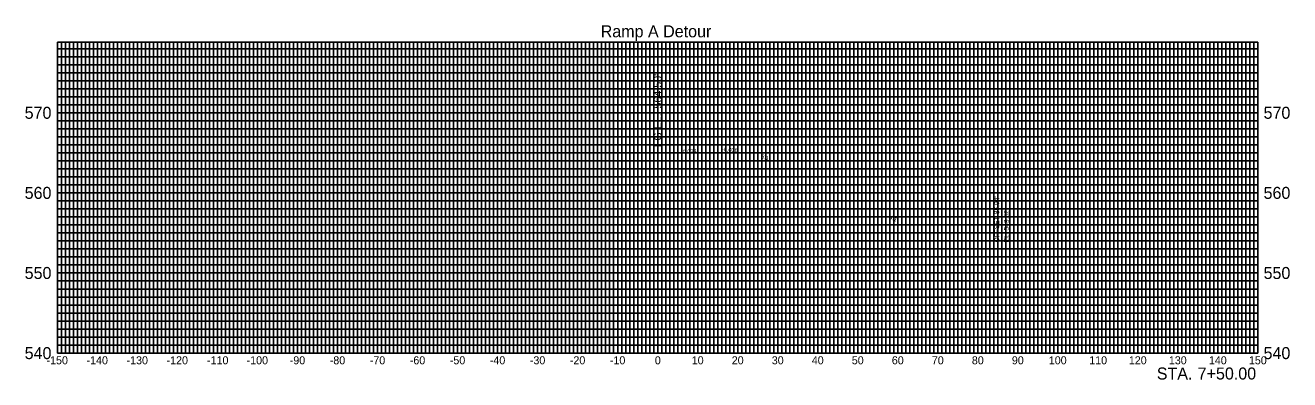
# Model space of a CAD drawing. Extents: x -158 to 158, y 533 to 622.
import ezdxf

# ---------------------------------------------------------------- set-up
doc = ezdxf.new("R2010")
doc.units = 0
for name, color, linetype in [('DES - SHEET - Light Grid', 7, 'Continuous'), ('DES - SHEET - Linework', 7, 'Continuous'), ('DES - XS - Proposed - Finished Grade Slopes Text', 7, 'Continuous'), ('DES - XS - Proposed - Text', 7, 'Continuous')]:
    doc.layers.add(name, color=color, linetype=linetype)

msp = doc.modelspace()

# ---------------------------------------------------------------- linework, layer by layer
at = {"layer": 'DES - SHEET - Light Grid'}
for p, q in [((-149, 540), (-149, 617.64)), ((-148, 540), (-148, 617.64)), ((-147, 540), (-147, 617.64)), ((-146, 540), (-146, 617.64)), ((-145, 540), (-145, 617.64)), ((-144, 540), (-144, 617.64)), ((-143, 540), (-143, 617.64)), ((-142, 540), (-142, 617.64)), ((-141, 540), (-141, 617.64)), ((-139, 540), (-139, 617.64)), ((-138, 540), (-138, 617.64)), ((-137, 540), (-137, 617.64)), ((-136, 540), (-136, 617.64)), ((-135, 540), (-135, 617.64)), ((-134, 540), (-134, 617.64)), ((-133, 540), (-133, 617.64)), ((-132, 540), (-132, 617.64)), ((-131, 540), (-131, 617.64)), ((-129, 540), (-129, 617.64)), ((-128, 540), (-128, 617.64)), ((-127, 540), (-127, 617.64)), ((-126, 540), (-126, 617.64)), ((-125, 540), (-125, 617.64)), ((-124, 540), (-124, 617.64)), ((-123, 540), (-123, 617.64)), ((-122, 540), (-122, 617.64)), ((-121, 540), (-121, 617.64)), ((-119, 540), (-119, 617.64)), ((-118, 540), (-118, 617.64)), ((-117, 540), (-117, 617.64)), ((-116, 540), (-116, 617.64)), ((-115, 540), (-115, 617.64)), ((-114, 540), (-114, 617.64)), ((-113, 540), (-113, 617.64)), ((-112, 540), (-112, 617.64)), ((-111, 540), (-111, 617.64)), ((-109, 540), (-109, 617.64)), ((-108, 540), (-108, 617.64)), ((-107, 540), (-107, 617.64)), ((-106, 540), (-106, 617.64)), ((-105, 540), (-105, 617.64)), ((-104, 540), (-104, 617.64)), ((-103, 540), (-103, 617.64)), ((-102, 540), (-102, 617.64)), ((-101, 540), (-101, 617.64)), ((-99, 540), (-99, 617.64)), ((-98, 540), (-98, 617.64)), ((-97, 540), (-97, 617.64)), ((-96, 540), (-96, 617.64)), ((-95, 540), (-95, 617.64)), ((-94, 540), (-94, 617.64)), ((-93, 540), (-93, 617.64)), ((-92, 540), (-92, 617.64)), ((-91, 540), (-91, 617.64)), ((-89, 540), (-89, 617.64)), ((-88, 540), (-88, 617.64)), ((-87, 540), (-87, 617.64)), ((-86, 540), (-86, 617.64)), ((-85, 540), (-85, 617.64)), ((-84, 540), (-84, 617.64)), ((-83, 540), (-83, 617.64)), ((-82, 540), (-82, 617.64)), ((-81, 540), (-81, 617.64)), ((-79, 540), (-79, 617.64)), ((-78, 540), (-78, 617.64)), ((-77, 540), (-77, 617.64)), ((-76, 540), (-76, 617.64)), ((-75, 540), (-75, 617.64)), ((-74, 540), (-74, 617.64)), ((-73, 540), (-73, 617.64)), ((-72, 540), (-72, 617.64)), ((-71, 540), (-71, 617.64)), ((-69, 540), (-69, 617.64)), ((-68, 540), (-68, 617.64)), ((-67, 540), (-67, 617.64)), ((-66, 540), (-66, 617.64)), ((-65, 540), (-65, 617.64)), ((-64, 540), (-64, 617.64)), ((-63, 540), (-63, 617.64)), ((-62, 540), (-62, 617.64)), ((-61, 540), (-61, 617.64)), ((-59, 540), (-59, 617.64)), ((-58, 540), (-58, 617.64)), ((-57, 540), (-57, 617.64)), ((-56, 540), (-56, 617.64)), ((-55, 540), (-55, 617.64)), ((-54, 540), (-54, 617.64)), ((-53, 540), (-53, 617.64)), ((-52, 540), (-52, 617.64)), ((-51, 540), (-51, 617.64)), ((-49, 540), (-49, 617.64)), ((-48, 540), (-48, 617.64)), ((-47, 540), (-47, 617.64)), ((-46, 540), (-46, 617.64)), ((-45, 540), (-45, 617.64)), ((-44, 540), (-44, 617.64)), ((-43, 540), (-43, 617.64)), ((-42, 540), (-42, 617.64)), ((-41, 540), (-41, 617.64)), ((-39, 540), (-39, 617.64)), ((-38, 540), (-38, 617.64)), ((-37, 540), (-37, 617.64)), ((-36, 540), (-36, 617.64)), ((-35, 540), (-35, 617.64)), ((-34, 540), (-34, 617.64)), ((-33, 540), (-33, 617.64)), ((-32, 540), (-32, 617.64)), ((-31, 540), (-31, 617.64)), ((-29, 540), (-29, 617.64)), ((-28, 540), (-28, 617.64)), ((-27, 540), (-27, 617.64)), ((-26, 540), (-26, 617.64)), ((-25, 540), (-25, 617.64)), ((-24, 540), (-24, 617.64)), ((-23, 540), (-23, 617.64)), ((-22, 540), (-22, 617.64)), ((-21, 540), (-21, 617.64)), ((-19, 540), (-19, 617.64)), ((-18, 540), (-18, 617.64)), ((-17, 540), (-17, 617.64)), ((-16, 540), (-16, 617.64)), ((-15, 540), (-15, 617.64)), ((-14, 540), (-14, 617.64)), ((-13, 540), (-13, 617.64)), ((-12, 540), (-12, 617.64)), ((-11, 540), (-11, 617.64)), ((-9, 540), (-9, 617.64)), ((-8, 540), (-8, 617.64)), ((-7, 540), (-7, 617.64)), ((-6, 540), (-6, 617.64)), ((-5, 540), (-5, 617.64)), ((-4, 540), (-4, 617.64)), ((-3, 540), (-3, 617.64)), ((-2, 540), (-2, 617.64)), ((-1, 540), (-1, 617.64)), ((1, 540), (1, 617.64)), ((2, 540), (2, 617.64)), ((3, 540), (3, 617.64)), ((4, 540), (4, 617.64)), ((5, 540), (5, 617.64)), ((6, 540), (6, 617.64)), ((7, 540), (7, 617.64)), ((8, 540), (8, 617.64)), ((9, 540), (9, 617.64)), ((11, 540), (11, 617.64)), ((12, 540), (12, 617.64)), ((13, 540), (13, 617.64)), ((14, 540), (14, 617.64)), ((15, 540), (15, 617.64)), ((16, 540), (16, 617.64)), ((17, 540), (17, 617.64)), ((18, 540), (18, 617.64)), ((19, 540), (19, 617.64)), ((21, 540), (21, 617.64)), ((22, 540), (22, 617.64)), ((23, 540), (23, 617.64)), ((24, 540), (24, 617.64)), ((25, 540), (25, 617.64)), ((26, 540), (26, 617.64)), ((27, 540), (27, 617.64)), ((28, 540), (28, 617.64)), ((29, 540), (29, 617.64)), ((31, 540), (31, 617.64)), ((32, 540), (32, 617.64)), ((33, 540), (33, 617.64)), ((34, 540), (34, 617.64)), ((35, 540), (35, 617.64)), ((36, 540), (36, 617.64)), ((37, 540), (37, 617.64)), ((38, 540), (38, 617.64)), ((39, 540), (39, 617.64)), ((41, 540), (41, 617.64)), ((42, 540), (42, 617.64)), ((43, 540), (43, 617.64)), ((44, 540), (44, 617.64)), ((45, 540), (45, 617.64)), ((46, 540), (46, 617.64)), ((47, 540), (47, 617.64)), ((48, 540), (48, 617.64)), ((49, 540), (49, 617.64)), ((51, 540), (51, 617.64)), ((52, 540), (52, 617.64)), ((53, 540), (53, 617.64)), ((54, 540), (54, 617.64)), ((55, 540), (55, 617.64)), ((56, 540), (56, 617.64)), ((57, 540), (57, 617.64)), ((58, 540), (58, 617.64)), ((59, 540), (59, 617.64)), ((61, 540), (61, 617.64)), ((62, 540), (62, 617.64)), ((63, 540), (63, 617.64)), ((64, 540), (64, 617.64)), ((65, 540), (65, 617.64)), ((66, 540), (66, 617.64)), ((67, 540), (67, 617.64)), ((68, 540), (68, 617.64)), ((69, 540), (69, 617.64)), ((71, 540), (71, 617.64)), ((72, 540), (72, 617.64)), ((73, 540), (73, 617.64)), ((74, 540), (74, 617.64)), ((75, 540), (75, 617.64)), ((76, 540), (76, 617.64)), ((77, 540), (77, 617.64)), ((78, 540), (78, 617.64)), ((79, 540), (79, 617.64)), ((81, 540), (81, 617.64)), ((82, 540), (82, 617.64)), ((83, 540), (83, 617.64)), ((84, 540), (84, 617.64)), ((85, 540), (85, 617.64)), ((86, 540), (86, 617.64)), ((87, 540), (87, 617.64)), ((88, 540), (88, 617.64)), ((89, 540), (89, 617.64)), ((91, 540), (91, 617.64)), ((92, 540), (92, 617.64)), ((93, 540), (93, 617.64)), ((94, 540), (94, 617.64)), ((95, 540), (95, 617.64)), ((96, 540), (96, 617.64)), ((97, 540), (97, 617.64)), ((98, 540), (98, 617.64)), ((99, 540), (99, 617.64)), ((101, 540), (101, 617.64)), ((102, 540), (102, 617.64)), ((103, 540), (103, 617.64)), ((104, 540), (104, 617.64)), ((105, 540), (105, 617.64)), ((106, 540), (106, 617.64)), ((107, 540), (107, 617.64)), ((108, 540), (108, 617.64)), ((109, 540), (109, 617.64)), ((111, 540), (111, 617.64)), ((112, 540), (112, 617.64)), ((113, 540), (113, 617.64)), ((114, 540), (114, 617.64)), ((115, 540), (115, 617.64)), ((116, 540), (116, 617.64)), ((117, 540), (117, 617.64)), ((118, 540), (118, 617.64)), ((119, 540), (119, 617.64)), ((121, 540), (121, 617.64)), ((122, 540), (122, 617.64)), ((123, 540), (123, 617.64)), ((124, 540), (124, 617.64)), ((125, 540), (125, 617.64)), ((126, 540), (126, 617.64)), ((127, 540), (127, 617.64)), ((128, 540), (128, 617.64)), ((129, 540), (129, 617.64)), ((131, 540), (131, 617.64)), ((132, 540), (132, 617.64)), ((133, 540), (133, 617.64)), ((134, 540), (134, 617.64)), ((135, 540), (135, 617.64)), ((136, 540), (136, 617.64)), ((137, 540), (137, 617.64)), ((138, 540), (138, 617.64)), ((139, 540), (139, 617.64)), ((141, 540), (141, 617.64)), ((142, 540), (142, 617.64)), ((143, 540), (143, 617.64)), ((144, 540), (144, 617.64)), ((145, 540), (145, 617.64)), ((146, 540), (146, 617.64)), ((147, 540), (147, 617.64)), ((148, 540), (148, 617.64)), ((149, 540), (149, 617.64)), ((-150, 616), (150, 616)), ((-150, 614), (150, 614)), ((-150, 612), (150, 612)), ((-150, 610), (150, 610)), ((-150, 608), (150, 608)), ((-150, 606), (150, 606)), ((-150, 604), (150, 604)), ((-150, 602), (150, 602)), ((-150, 598), (150, 598)), ((-150, 596), (150, 596)), ((-150, 594), (150, 594)), ((-150, 592), (150, 592)), ((-150, 590), (150, 590)), ((-150, 588), (150, 588)), ((-150, 586), (150, 586)), ((-150, 584), (150, 584)), ((-150, 582), (150, 582)), ((-150, 578), (150, 578)), ((-150, 576), (150, 576)), ((-150, 574), (150, 574)), ((-150, 572), (150, 572)), ((-150, 570), (150, 570)), ((-150, 568), (150, 568)), ((-150, 566), (150, 566)), ((-150, 564), (150, 564)), ((-150, 562), (150, 562)), ((-150, 558), (150, 558)), ((-150, 556), (150, 556)), ((-150, 554), (150, 554)), ((-150, 552), (150, 552)), ((-150, 550), (150, 550)), ((-150, 548), (150, 548)), ((-150, 546), (150, 546)), ((-150, 544), (150, 544)), ((-150, 542), (150, 542))]:
    msp.add_line(p, q, dxfattribs=at)
at = {"layer": 'DES - SHEET - Linework'}
for p, q in [((-150, 617.64), (150, 617.64)), ((-150, 540), (-150, 617.64)), ((-140, 540), (-140, 617.64)), ((-130, 540), (-130, 617.64)), ((-120, 540), (-120, 617.64)), ((-110, 540), (-110, 617.64)), ((-100, 540), (-100, 617.64)), ((-90, 540), (-90, 617.64)), ((-80, 540), (-80, 617.64)), ((-70, 540), (-70, 617.64)), ((-60, 540), (-60, 617.64)), ((-50, 540), (-50, 617.64)), ((-40, 540), (-40, 617.64)), ((-30, 540), (-30, 617.64)), ((-20, 540), (-20, 617.64)), ((-10, 540), (-10, 617.64)), ((0, 540), (0, 617.64)), ((10, 540), (10, 617.64)), ((20, 540), (20, 617.64)), ((30, 540), (30, 617.64)), ((40, 540), (40, 617.64)), ((50, 540), (50, 617.64)), ((60, 540), (60, 617.64)), ((70, 540), (70, 617.64)), ((80, 540), (80, 617.64)), ((90, 540), (90, 617.64)), ((100, 540), (100, 617.64)), ((110, 540), (110, 617.64)), ((120, 540), (120, 617.64)), ((130, 540), (130, 617.64)), ((140, 540), (140, 617.64)), ((150, 540), (150, 617.64)), ((-150, 600), (150, 600)), ((-150, 580), (150, 580)), ((-150, 560), (150, 560)), ((-150, 540), (150, 540))]:
    msp.add_line(p, q, dxfattribs=at)

# ---------------------------------------------------------------- texts
at = {"layer": 'DES - XS - Proposed - Finished Grade Slopes Text'}
for s, height, rotation, p in [('0.034', 1, 3.922, (6.29, 589.74)), ('-0.036', 1, 355.9137, (16.06, 590.4)), ('6:1', 1, 341.5651, (25.78, 588.72)), ("85.94'", 1.2, 90, (85.34, 574.68)), ('549.62', 1.2, 90, (87.74, 570.61)), ('4:1', 1, 333.4349, (57.79, 573.61)), ('OFFSET ', 1.2, 90, (85.34, 567.63)), ('EL. ', 1.2, 90, (87.74, 567.63))]:
    msp.add_text(s, height=height, rotation=rotation, dxfattribs=at).set_placement(p)
at = {"layer": 'DES - XS - Proposed - Text'}
for s, height, p in [('Ramp A Detour', 3, (-14.24, 618.84)), ('570', 3, (-158.19, 598.5)), ('570', 3, (151.41, 598.5)), ('560', 3, (-158.19, 578.5)), ('560', 3, (151.41, 578.5)), ('550', 3, (-158.19, 558.5)), ('550', 3, (151.41, 558.5)), ('540', 3, (-158.19, 538.5)), ('540', 3, (151.41, 538.5)), ('-150', 2, (-152.73, 537.2)), ('-140', 2, (-142.73, 537.2)), ('-130', 2, (-132.73, 537.2)), ('-120', 2, (-122.73, 537.2)), ('-110', 2, (-112.62, 537.2)), ('-100', 2, (-102.73, 537.2)), ('-90', 2, (-91.95, 537.2)), ('-80', 2, (-81.95, 537.2)), ('-70', 2, (-71.95, 537.2)), ('-60', 2, (-61.95, 537.2)), ('-50', 2, (-51.95, 537.2)), ('-40', 2, (-41.95, 537.2)), ('-30', 2, (-31.95, 537.2)), ('-20', 2, (-21.95, 537.2)), ('-10', 2, (-11.95, 537.2)), ('0', 2, (-0.71, 537.2)), ('10', 2, (8.51, 537.2)), ('20', 2, (18.51, 537.2)), ('30', 2, (28.51, 537.2)), ('40', 2, (38.51, 537.2)), ('50', 2, (48.51, 537.2)), ('60', 2, (58.51, 537.2)), ('70', 2, (68.51, 537.2)), ('80', 2, (78.51, 537.2)), ('90', 2, (88.51, 537.2)), ('100', 2, (97.74, 537.2)), ('110', 2, (107.84, 537.2)), ('120', 2, (117.74, 537.2)), ('130', 2, (127.74, 537.2)), ('140', 2, (137.74, 537.2)), ('150', 2, (147.74, 537.2)), (' STA. ', 3, (123.61, 533.4)), ('7+50.00', 3, (134.94, 533.4))]:
    msp.add_text(s, height=height, dxfattribs=at).set_placement(p)
for s, p in [("564.50'", (1, 601.04)), ('FG EL. ', (1, 591.41))]:
    msp.add_text(s, height=2, rotation=90, dxfattribs=at).set_placement(p)

doc.saveas('drawing.dxf')
